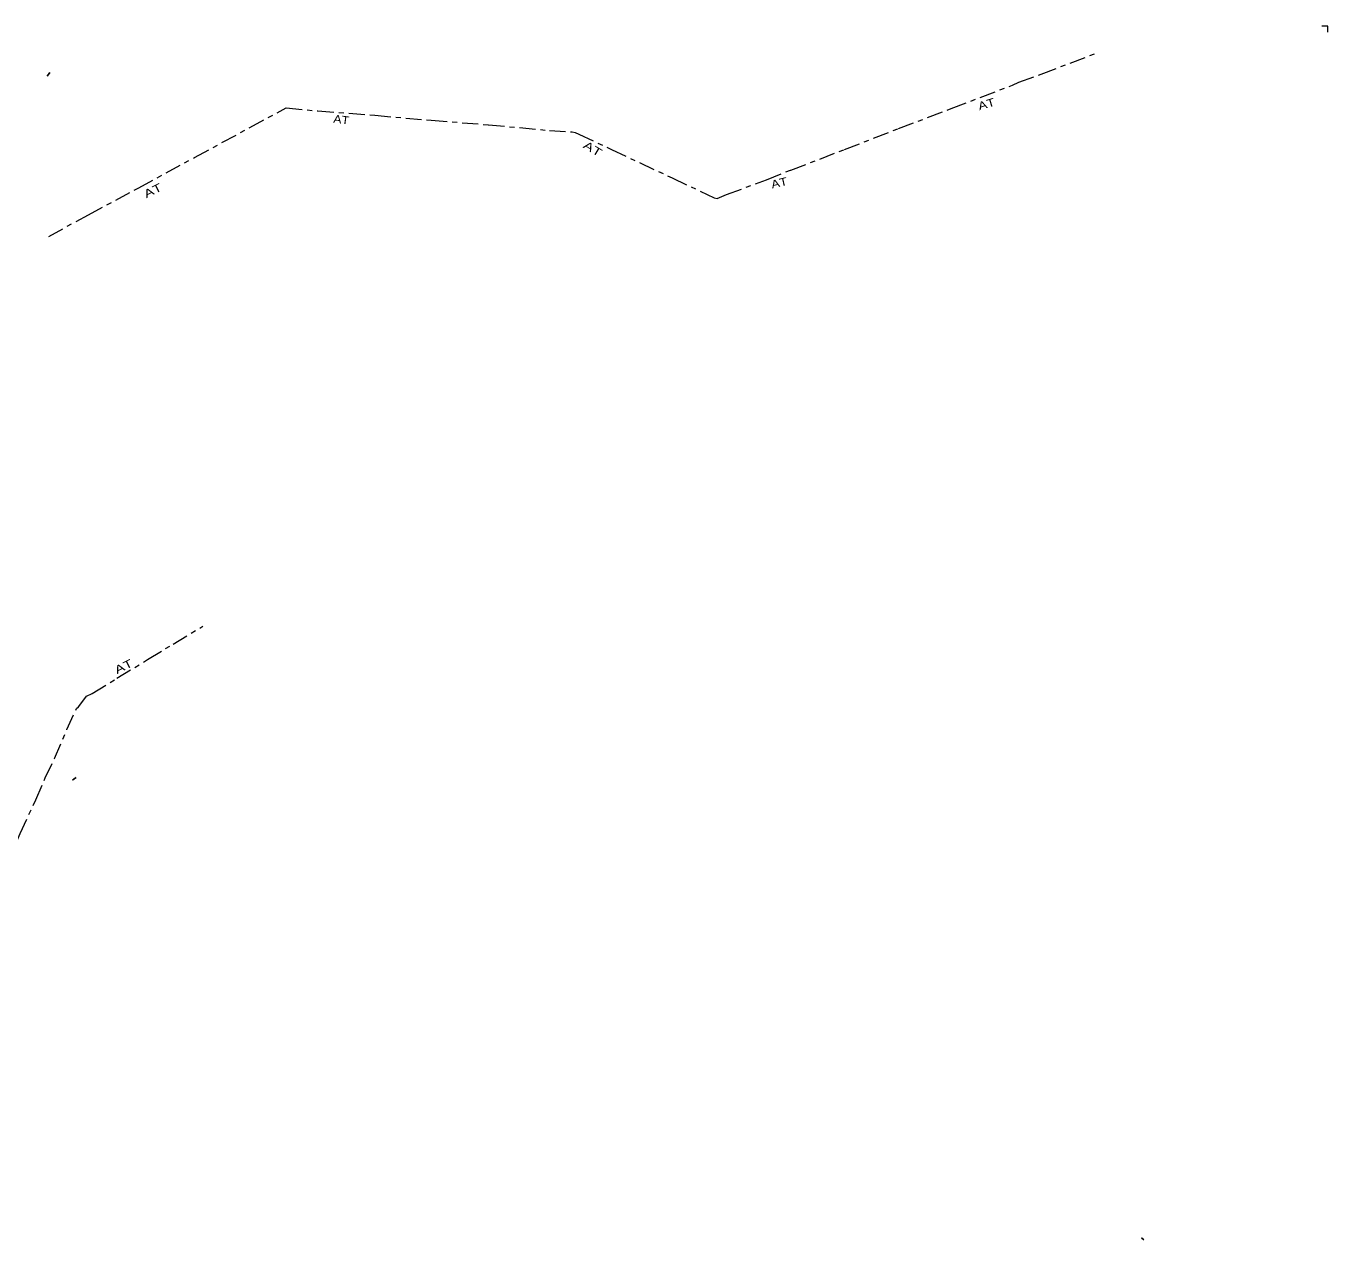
# Model space of a CAD drawing. Extents: x 552.5 to 605.3, y 7843.5 to 7899.1.
# Drawn here: x 579.23 to 605.25, y 7874.58 to 7898.84 of the extents above; entities that cross this region are included whole.
import ezdxf
from ezdxf.enums import TextEntityAlignment as Align

# ---------------------------------------------------------------- set-up
doc = ezdxf.new("R2010")
doc.units = 0
doc.header["$LTSCALE"] = 0.064
doc.linetypes.add('DOT_DASHED', pattern=[7.7, 5, -1.2, 0.3, -1.2])
for name, color, linetype, lineweight in [('24', 7, 'Continuous', 25), ('56', 7, 'DOT_DASHED', 13), ('63', 7, 'Continuous', 13)]:
    doc.layers.add(name, color=color, linetype=linetype, lineweight=lineweight)
doc.layers.add('61', color=7, linetype='Continuous')

msp = doc.modelspace()

# ---------------------------------------------------------------- linework, layer by layer
at = {"layer": '24'}
msp.add_line((601.5222, 7874.6267), (601.5696, 7874.5843), dxfattribs=at)
for points in [[(579.6517, 7897.8425), (579.6884, 7897.8901), (579.7077, 7897.9121)], [(580.1545, 7883.773), (580.1917, 7883.8008), (580.2312, 7883.8245)]]:
    msp.add_lwpolyline(points, dxfattribs=at)
at = {"layer": '56'}
for points in [[(579.6845, 7894.637), (580.4754, 7895.0703), (581.4839, 7895.6105), (582.5994, 7896.2153), (583.7019, 7896.8126), (584.4304, 7897.2037), (585.0645, 7897.1445), (586.2002, 7897.0578), (587.3267, 7896.9583), (588.4735, 7896.8679), (589.6922, 7896.7555), (590.144, 7896.7241), (590.203, 7896.7131), (590.2786, 7896.6817), (590.9294, 7896.3757), (592.1426, 7895.806), (592.9815, 7895.4114), (593.0405, 7895.3948), (593.2304, 7895.4722), (594.0269, 7895.7691), (594.5136, 7895.9627), (595.5904, 7896.3738), (596.6653, 7896.7924), (597.7217, 7897.1924), (598.9497, 7897.6608), (599.075, 7897.7182), (599.5194, 7897.8802), (600.6339, 7898.3036)], [(578.2841, 7876.6789), (578.187, 7877.5019), (578.1063, 7878.1586), (578.0076, 7879.0326), (577.9105, 7879.9099), (577.8989, 7880.0218), (577.9055, 7880.0515), (577.9977, 7880.2407), (578.3878, 7881.0933), (578.7285, 7881.8505), (579.112, 7882.7031), (579.4214, 7883.3779), (579.614, 7883.8157), (579.7983, 7884.2058), (580.0469, 7884.7852), (580.2375, 7885.2039), (580.2791, 7885.2377), (580.3811, 7885.3778), (580.4344, 7885.4505), (580.5505, 7885.5061), (581.046, 7885.8073), (581.6599, 7886.1826), (582.1701, 7886.4904), (582.7615, 7886.8475)]]:
    msp.add_lwpolyline(points, dxfattribs=at)
at = {"layer": '63'}
msp.add_lwpolyline([(605.2523, 7898.7176), (605.2523, 7898.8408), (605.1309, 7898.8408)], dxfattribs=at)

# ---------------------------------------------------------------- texts
at = {"layer": '61'}
for rotation, width, p in [(16.699, 1.25, (598.44916, 7897.20505)), (352.529, 1.15, (585.52015, 7896.89188)), (329.066, 1.4, (590.51458, 7896.31919)), (13.325, 1.2, (594.30231, 7895.62971)), (26.565, 1.35, (581.79952, 7895.48201)), (26.565, 1.35, (581.21412, 7885.97201))]:
    msp.add_text('AT', height=0.16, rotation=rotation, dxfattribs=dict(at, width=width)).set_placement(p, align=Align.CENTER)

doc.saveas('drawing.dxf')
